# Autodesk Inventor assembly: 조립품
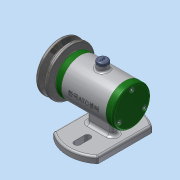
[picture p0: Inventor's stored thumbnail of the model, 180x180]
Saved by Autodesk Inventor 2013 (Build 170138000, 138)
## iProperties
Created: 2017-12
Part Number: 조립품
Document SubType Name: Assembly
Designer: dgall
Author: dgall
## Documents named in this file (14)
- C:\Users\dgall\Desktop\471207V1020\조립품.iam
- C:\Users\dgall\Desktop\471207V1020\본체.ipt
- C:\Users\dgall\Desktop\471207V1020\축.ipt
- C:\Users\dgall\Desktop\471207V1020\베어링 15 x 32 x 9.ipt
- C:\Users\dgall\Desktop\471207V1020\뒤커버.ipt
- C:\Users\dgall\Desktop\471207V1020\앞커버.ipt
- C:\Users\dgall\Desktop\471207V1020\볼트 M4 x 12.ipt
- C:\Users\dgall\Desktop\471207V1020\오일 실 15 25 7.ipt
- C:\Users\dgall\Desktop\471207V1020\키 3 x 3 x 12.ipt
- C:\Users\dgall\Desktop\471207V1020\V벨트풀리.ipt
- C:\Users\dgall\Desktop\471207V1020\와셔 8x17.ipt
- C:\Users\dgall\Desktop\471207V1020\스프링와셔 8.ipt
- C:\Users\dgall\Desktop\471207V1020\너트 M 8.ipt
- C:\Users\dgall\Desktop\471207V1020\고무캡.ipt
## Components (2 placed, 2 different names)
1. V벨트풀리:1 — 각도:2
2. 고무캡:1
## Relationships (1: Angle 1)
- 각도:2 [Angle]: V벨트풀리:1
